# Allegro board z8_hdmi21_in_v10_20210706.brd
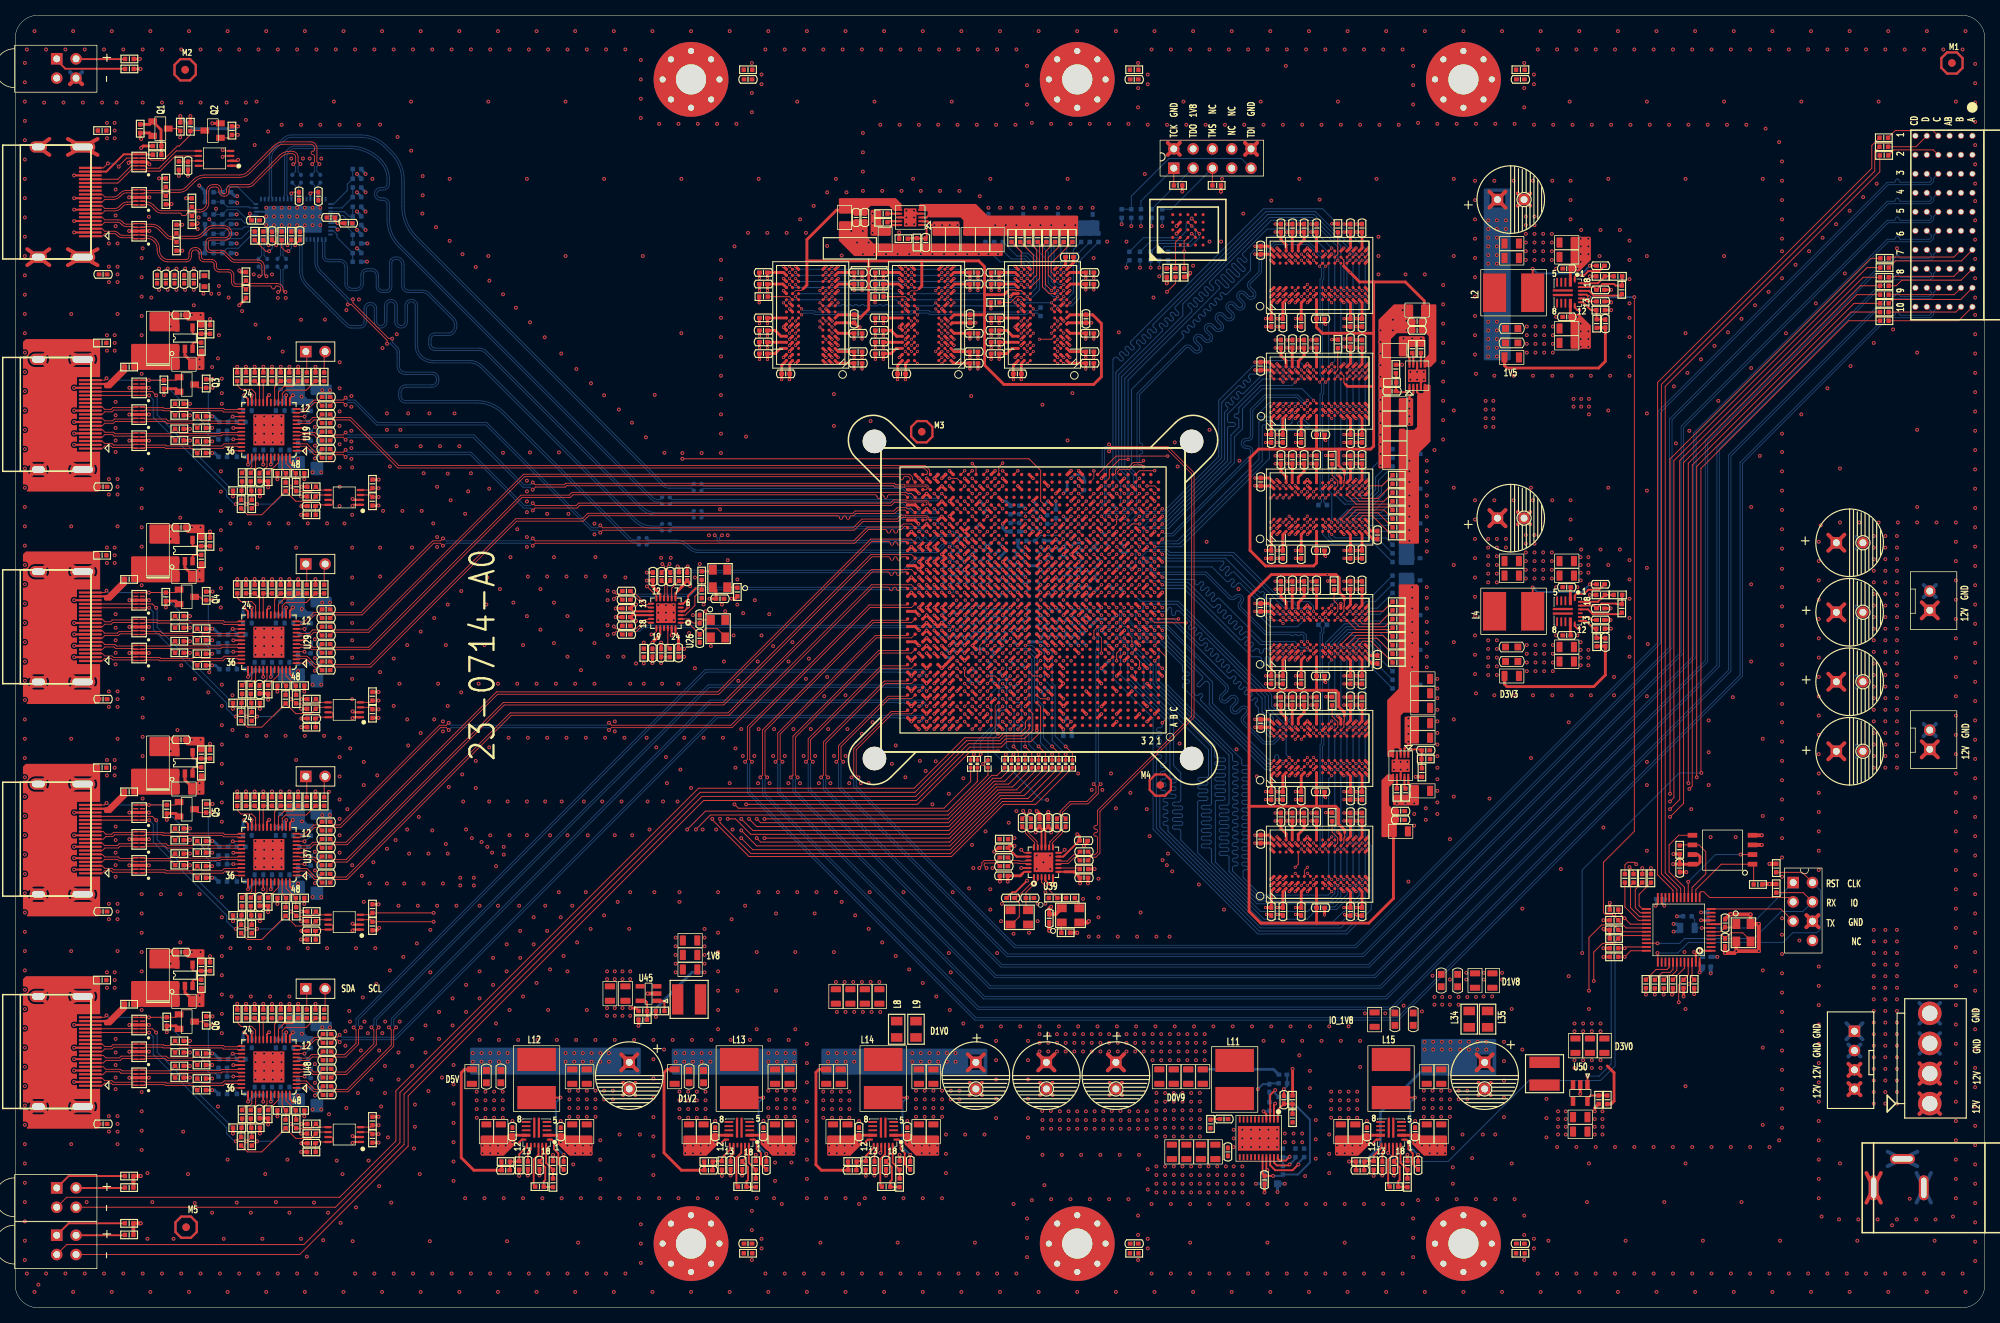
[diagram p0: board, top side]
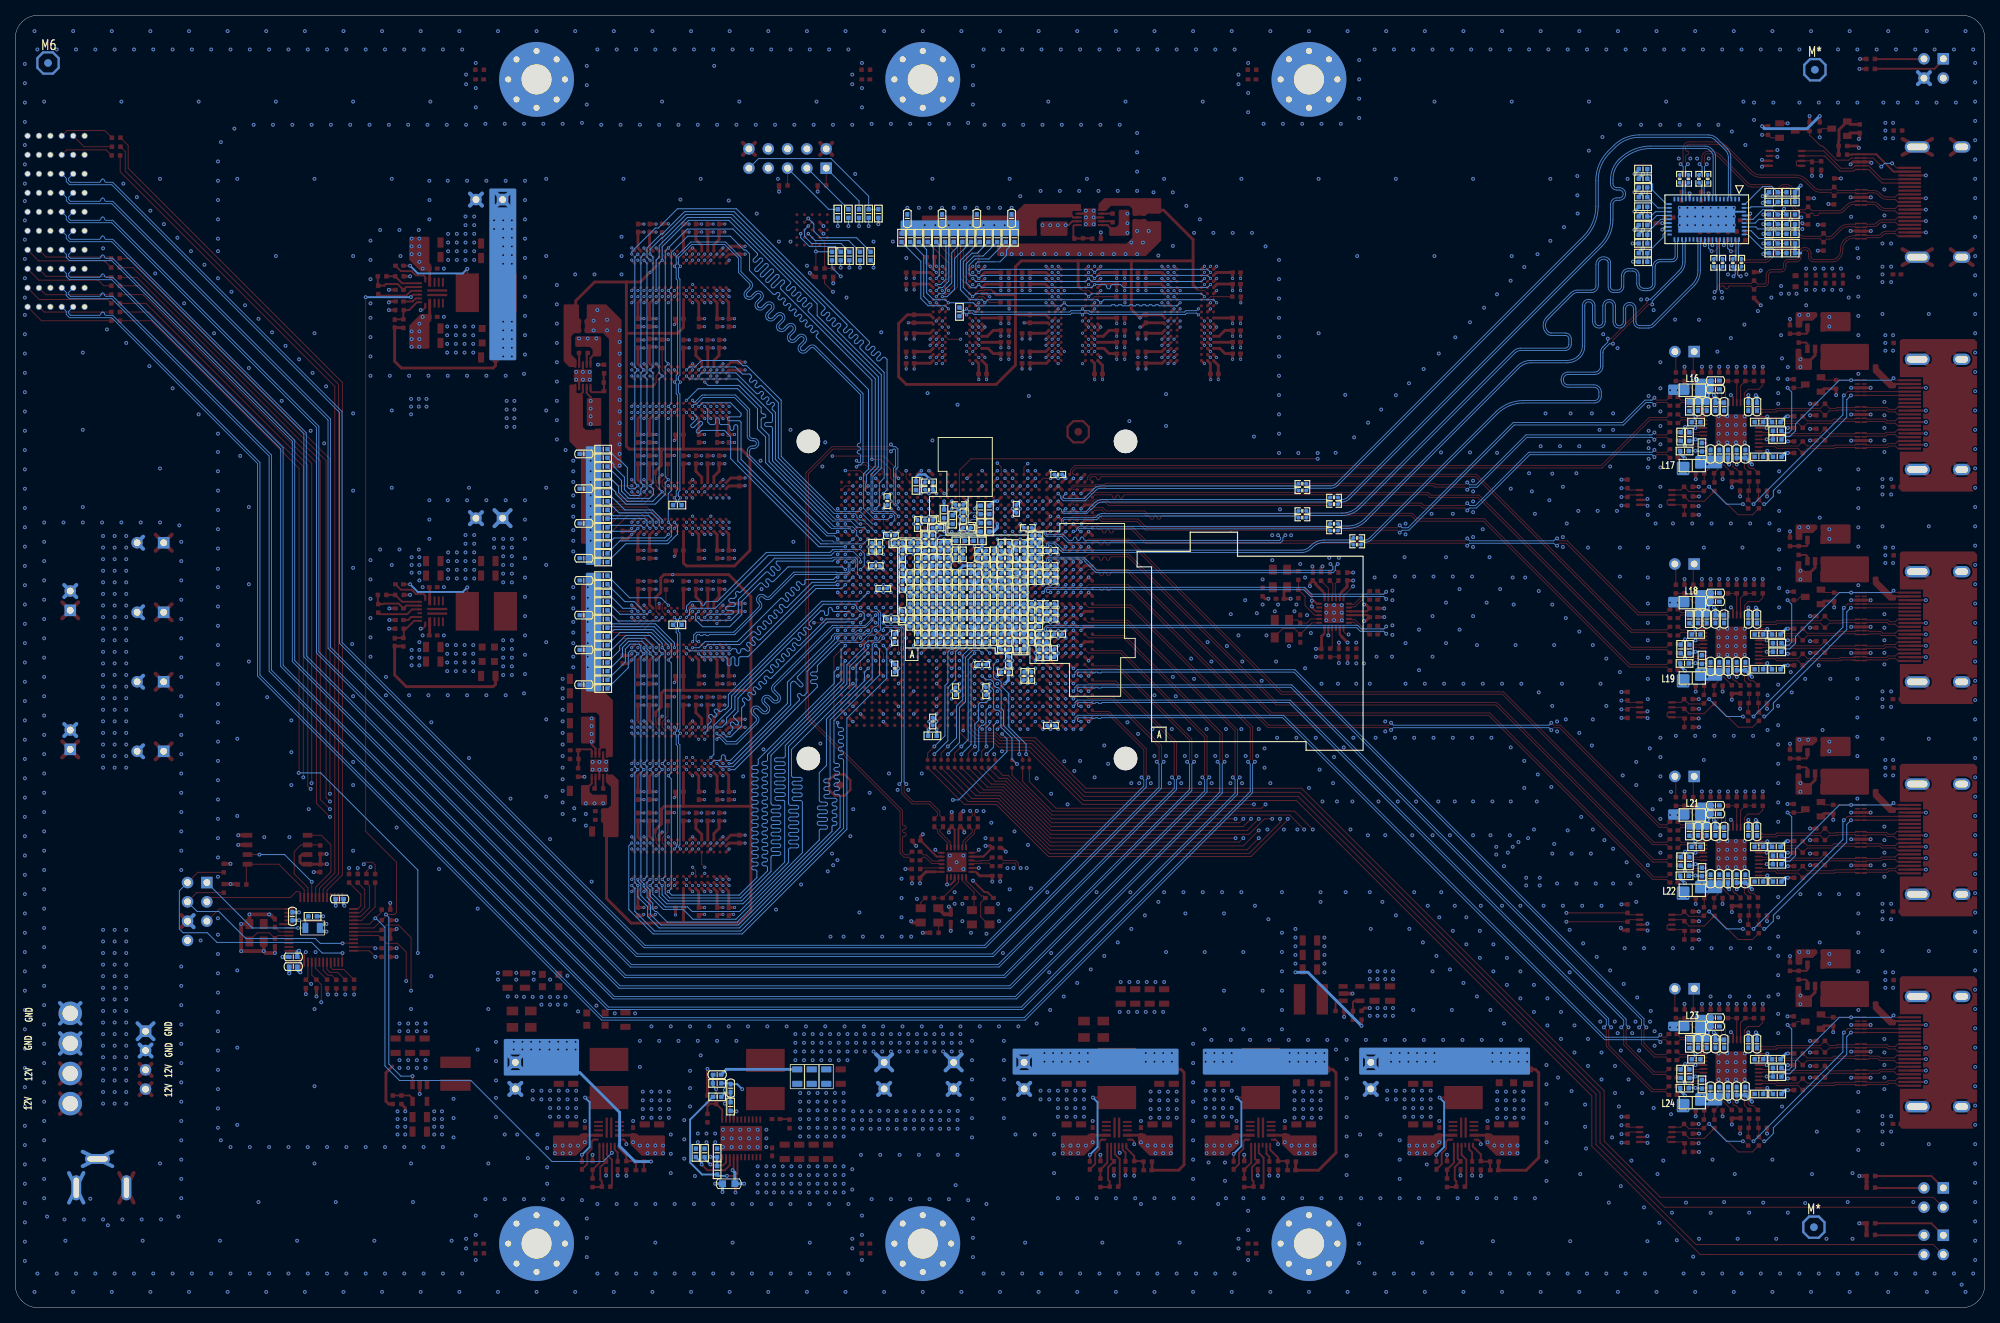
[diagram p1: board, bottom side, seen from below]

Outline 259.08 x 170.05 mm; copper layers: TOP, 02_GND1, 03_SIG1, 04_PWR1, 05_PWR2, 06_SIG2, 07_GND2, BOTTOM. Coordinates in mm from the lower left corner of the outline.
Outline path: 0,167 0,3.05 arc(0.89,0.89) 3.05,0 256.03,0 arc(258.19,0.89) 259.08,3.05 259.08,167 arc(258.19,169.16) 256.03,170.05 3.05,170.05 arc(0.89,169.16) 0,167

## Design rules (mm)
constraint set DEFAULT: min track width 0.127
net group CONN_RCK: nets CONN_RCK+ CONN_RCK-
net group CONN_TX0: nets CONN_TX+0 CONN_TX-0
net group CONN_TX1: nets CONN_TX+1 CONN_TX-1
net group CONN_TX2: nets CONN_TX+2 CONN_TX-2
net group CONN_TX3: nets CONN_TX+3 CONN_TX-3
net group CONN_TX4: nets CONN_TX+4 CONN_TX-4
net group CONN_TX5: nets CONN_TX+5 CONN_TX-5
net group CONN_TX6: nets CONN_TX+6 CONN_TX-6
net group CONN_TX7: nets CONN_TX+7 CONN_TX-7
net group CONN_TX_RCK: nets CONN_TX_RCK+ CONN_TX_RCK-
net group DDR3A: nets SI_DDR3A_N SI_DDR3A_P
net group DDR3A_133.33M: nets DDR3A_N DDR3A_P
net group DDR3B: nets SI_DDR3B_N SI_DDR3B_P
net group DDR3B_133.33M: nets DDR3B_N DDR3B_P
net group DDR3C: nets SI_DDR3C_N SI_DDR3C_P
net group DDR3C_133.33M: nets DDR3C_N DDR3C_P
net group HDMI20_RX_RCK+: nets HDMI20_RX_RCK+ HM20_RX_RCK+
net group HDMI20_RX_RCK-: nets HDMI20_RX_RCK- HM20_RX_RCK-
net group HDMI21_RX_RCK: nets HDMI21_RX_RCK+ HDMI21_RX_RCK-
net group HDMI_1_TCX: nets HDMI_1_TCX+ HDMI_1_TCX-
net group HDMI_1_TX0: nets HDMI_1_TX0+ HDMI_1_TX0-
net group HDMI_1_TX1: nets HDMI_1_TX1+ HDMI_1_TX1-
net group HDMI_1_TX2: nets HDMI_1_TX2+ HDMI_1_TX2-
net group HDMI_2_TCX: nets HDMI_2_TCX+ HDMI_2_TCX-
net group HDMI_2_TX0: nets HDMI_2_TX0+ HDMI_2_TX0-
net group HDMI_2_TX1: nets HDMI_2_TX1+ HDMI_2_TX1-
net group HDMI_2_TX2: nets HDMI_2_TX2+ HDMI_2_TX2-
net group HDMI_3_TCX: nets HDMI_3_TCX+ HDMI_3_TCX-
net group HDMI_3_TX0: nets HDMI_3_TX0+ HDMI_3_TX0-
net group HDMI_3_TX1: nets HDMI_3_TX1+ HDMI_3_TX1-
net group HDMI_3_TX2: nets HDMI_3_TX2+ HDMI_3_TX2-
net group HDMI_4_TCX: nets HDMI_4_TCX+ HDMI_4_TCX-
net group HDMI_4_TX0: nets HDMI_4_TX0+ HDMI_4_TX0-
net group HDMI_4_TX1: nets HDMI_4_TX1+ HDMI_4_TX1-
net group HDMI_4_TX2: nets HDMI_4_TX2+ HDMI_4_TX2-
net group HDMI_RX0N: nets HDMI_RX0N HDMI_RXC0N
net group HDMI_RX0P: nets HDMI_RX0P HDMI_RXC0P
net group HDMI_RX1N: nets HDMI_RX1N HDMI_RXC1N
net group HDMI_RX1P: nets HDMI_RX1P HDMI_RXC1P
net group HDMI_RX2N: nets HDMI_RX2N HDMI_RXC2N
net group HDMI_RX2P: nets HDMI_RX2P HDMI_RXC2P
net group HDMI_RX3N: nets HDMI_RX3N HDMI_RXC3N
net group HDMI_RX3P: nets HDMI_RX3P HDMI_RXC3P
net group HM20_TX: nets HM20_TX+ HM20_TX-
net group HM20_TX_RCX: nets HM20_TX_RCX+ HM20_TX_RCX-
net group HM21_RX0+: nets HM21_RX0+ HM21RX0+
net group HM21_RX0-: nets HM21_RX0- HM21RX0-
net group HM21_RX1+: nets HM21_RX1+ HM21RX1+
net group HM21_RX1-: nets HM21_RX1- HM21RX1-
net group HM21_RX2+: nets HM21_RX2+ HM21RX2+
net group HM21_RX2-: nets HM21_RX2- HM21RX2-
net group HM21_RX3+: nets HM21_RX3+ HM21RX3+
net group HM21_RX3-: nets HM21_RX3- HM21RX3-
net group HM_1_TCX+: nets HM_1_TCX+ N22318988
net group HM_1_TCX-: nets HM_1_TCX- N22318990
net group HM_1_TX0+: nets HM_1_TX0+ N22318294
net group HM_1_TX0-: nets HM_1_TX0- N22318980
net group HM_1_TX1+: nets HM_1_TX1+ N22318019
net group HM_1_TX1-: nets HM_1_TX1- N22318021
net group HM_1_TX2+: nets HM_1_TX2+ N22318023
net group HM_1_TX2-: nets HM_1_TX2- N22318025
net group HM_2_TCX+: nets HM_2_TCX+ N22337253
net group HM_2_TCX-: nets HM_2_TCX- N22337255
net group HM_2_TX0+: nets HM_2_TX0+ N22336562
net group HM_2_TX0-: nets HM_2_TX0- N22337251
net group HM_2_TX1+: nets HM_2_TX1+ N22336290
net group HM_2_TX1-: nets HM_2_TX1- N22336292
net group HM_2_TX2+: nets HM_2_TX2+ N22336294
net group HM_2_TX2-: nets HM_2_TX2- N22336296
net group HM_3_TCX+: nets HM_3_TCX+ N22342658
net group HM_3_TCX-: nets HM_3_TCX- N22342660
net group HM_3_TX0+: nets HM_3_TX0+ N22341967
net group HM_3_TX0-: nets HM_3_TX0- N22342656
net group HM_3_TX1+: nets HM_3_TX1+ N22341695
net group HM_3_TX1-: nets HM_3_TX1- N22341697
net group HM_3_TX2+: nets HM_3_TX2+ N22341699
net group HM_3_TX2-: nets HM_3_TX2- N22341701
net group HM_4_TCX+: nets HM_4_TCX+ N22347962
net group HM_4_TCX-: nets HM_4_TCX- N22347964
net group HM_4_TX0+: nets HM_4_TX0+ N22347259
net group HM_4_TX0-: nets HM_4_TX0- N22347960
net group HM_4_TX1+: nets HM_4_TX1+ N22346984
net group HM_4_TX1-: nets HM_4_TX1- N22347001
net group HM_4_TX2+: nets HM_4_TX2+ N22347003
net group HM_4_TX2-: nets HM_4_TX2- N22347005
net group RC_F: nets HDMI21_RX+ HDMI21_RX-
net group RC_F_: nets RC_F_N RC_F_P
net group REFCLK_F: nets REFCLK_F_N REFCLK_F_P
net group CLS_PWR_PH: nets D1V8 D3V3 D5V D12V VCC_D0V9 VCC_DDR3 VCCIO_D3V0 VCCR_D1V0 VDD_PLL1 VDD_PLL2 VREF_DDR3_A VREF_DDR3_B VREF_DDR3_C VTT_DDR3_A VTT_DDR3_B VTT_DDR3_C
net group DDR3_A: nets DDR3_A_A0 DDR3_A_A1 DDR3_A_A2 DDR3_A_A3 DDR3_A_A5 DDR3_A_A6 DDR3_A_A7 DDR3_A_A8 DDR3_A_A9 DDR3_A_A10 DDR3_A_A11 DDR3_A_A12 DDR3_A_BA0 DDR3_A_BA1 DDR3_A_BA2 DDR3_A_CAS_N_0 DDR3_A_CK_0 DDR3_A_CK_N_0 DDR3_A_CKE_0 DDR3_A_CS_N_0 DDR3_A_ODT_0 DDR3_A_RAS_N_0 DDR3_A_RST_N_0 DDR3_A_WE_N_0
net group DDR3_A_D0: nets DDR3_A_DM0 DDR3_A_DQ0 DDR3_A_DQ1 DDR3_A_DQ2 DDR3_A_DQ3 DDR3_A_DQ4 DDR3_A_DQ5 DDR3_A_DQ6 DDR3_A_DQ7 DDR3_A_DQS0N DDR3_A_DQS0P
net group DDR3_A_D1: nets DDR3_A_DM1 DDR3_A_DQ8 DDR3_A_DQ9 DDR3_A_DQ10 DDR3_A_DQ11 DDR3_A_DQ12 DDR3_A_DQ13 DDR3_A_DQ14 DDR3_A_DQ15 DDR3_A_DQS1N DDR3_A_DQS1P
net group DDR3_A_D2: nets DDR3_A_DM2 DDR3_A_DQ16 DDR3_A_DQ17 DDR3_A_DQ18 DDR3_A_DQ19 DDR3_A_DQ20 DDR3_A_DQ21 DDR3_A_DQ22 DDR3_A_DQ23 DDR3_A_DQS2N DDR3_A_DQS2P
net group DDR3_A_D3: nets DDR3_A_DM3 DDR3_A_DQ24 DDR3_A_DQ25 DDR3_A_DQ26 DDR3_A_DQ27 DDR3_A_DQ28 DDR3_A_DQ29 DDR3_A_DQ30 DDR3_A_DQ31 DDR3_A_DQS3N DDR3_A_DQS3P
net group DDR3_A_D4: nets DDR3_A_DM4 DDR3_A_DQ32 DDR3_A_DQ33 DDR3_A_DQ34 DDR3_A_DQ35 DDR3_A_DQ36 DDR3_A_DQ37 DDR3_A_DQ38 DDR3_A_DQ39 DDR3_A_DQS4N DDR3_A_DQS4P
net group DDR3_B_D0: nets DDR3_B_DM0 DDR3_B_DQ0 DDR3_B_DQ1 DDR3_B_DQ2 DDR3_B_DQ3 DDR3_B_DQ4 DDR3_B_DQ5 DDR3_B_DQ6 DDR3_B_DQ7 DDR3_B_DQS0N DDR3_B_DQS0P
net group DDR3_B_D1: nets DDR3_B_DM1 DDR3_B_DQ8 DDR3_B_DQ9 DDR3_B_DQ10 DDR3_B_DQ11 DDR3_B_DQ12 DDR3_B_DQ13 DDR3_B_DQ14 DDR3_B_DQ15 DDR3_B_DQS1N DDR3_B_DQS1P
net group DDR3_B_D2: nets DDR3_B_DM2 DDR3_B_DQ16 DDR3_B_DQ17 DDR3_B_DQ18 DDR3_B_DQ19 DDR3_B_DQ20 DDR3_B_DQ21 DDR3_B_DQ22 DDR3_B_DQ23 DDR3_B_DQS2N DDR3_B_DQS2P
net group DDR3_B_D3: nets DDR3_B_DM3 DDR3_B_DQ24 DDR3_B_DQ25 DDR3_B_DQ26 DDR3_B_DQ27 DDR3_B_DQ28 DDR3_B_DQ29 DDR3_B_DQ30 DDR3_B_DQ31 DDR3_B_DQS3N DDR3_B_DQS3P
net group DDR3_B_D4: nets DDR3_B_DM4 DDR3_B_DQ32 DDR3_B_DQ33 DDR3_B_DQ34 DDR3_B_DQ35 DDR3_B_DQ36 DDR3_B_DQ37 DDR3_B_DQ38 DDR3_B_DQ39 DDR3_B_DQS4N DDR3_B_DQS4P
net group DDR3_C_D0: nets DDR3_C_DM0 DDR3_C_DQ0 DDR3_C_DQ1 DDR3_C_DQ2 DDR3_C_DQ3 DDR3_C_DQ4 DDR3_C_DQ5 DDR3_C_DQ6 DDR3_C_DQ7 DDR3_C_DQS0N DDR3_C_DQS0P
net group DDR3_C_D1: nets DDR3_C_DM1 DDR3_C_DQ8 DDR3_C_DQ9 DDR3_C_DQ10 DDR3_C_DQ11 DDR3_C_DQ12 DDR3_C_DQ13 DDR3_C_DQ14 DDR3_C_DQ15 DDR3_C_DQS1N DDR3_C_DQS1P
net group DDR3_C_D2: nets DDR3_C_DM2 DDR3_C_DQ16 DDR3_C_DQ17 DDR3_C_DQ18 DDR3_C_DQ19 DDR3_C_DQ20 DDR3_C_DQ21 DDR3_C_DQ22 DDR3_C_DQ23 DDR3_C_DQS2N DDR3_C_DQS2P
net group DDR3_C_D3: nets DDR3_C_DM3 DDR3_C_DQ24 DDR3_C_DQ25 DDR3_C_DQ26 DDR3_C_DQ27 DDR3_C_DQ28 DDR3_C_DQ29 DDR3_C_DQ30 DDR3_C_DQ31 DDR3_C_DQS3N DDR3_C_DQS3P
net group DDR3_C_D4: nets DDR3_C_DM4 DDR3_C_DQ32 DDR3_C_DQ33 DDR3_C_DQ34 DDR3_C_DQ35 DDR3_C_DQ36 DDR3_C_DQ37 DDR3_C_DQ38 DDR3_C_DQ39 DDR3_C_DQS4N DDR3_C_DQS4P
net group N22030720: nets N22030720
net group N22031163: nets N22031488
net group N22449835: nets N22449835
net group N22451844: nets N22451844
net group N22647875: nets N22647875
net group N22766094: nets N22766094
net group N22768239: nets N22768239

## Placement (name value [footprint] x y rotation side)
C1  0.1uF  [C0402]  96.39 161.61 0 top
C2  0.1uF  [C0402]  147.19 161.61 0 top
C3  0.1uF  [C0402]  197.99 161.61 0 top
C4  0.1uF  [C0402]  22.73 150.24 90 top
C5  0.1uF  [C0402]  37.34 146.24 270 top
C6  0.1uF  [C0402]  39.88 146.24 270 top
C7  270uF-NCC  [CAP196_POL_3_5MM]  196.72 145.8 0 top
C8  0.1uF  [C0402]  41.53 143.45 0 top
C9  10uF-08  [C0805]  109.09 143.45 270 top
C10  0.1uF  [C0402]  110.62 143.45 270 top
C11  0.1uF  [C0402]  111.76 143.45 270 top
C12  0.1uF  [C0402]  31.62 143.07 0 top
C13  1uF  [C0402]  43.82 142.68 180 top
C14  0.1uF  [C0402]  166.5 142.05 90 top
C15  0.1uF  [C0402]  168.02 142.05 90 top
C16  0.1uF  [C0402]  169.55 142.05 90 top
C17  0.1uF  [C0402]  171.2 142.05 90 top
C18  0.1uF  [C0402]  175.64 142.05 90 top
C19  0.1uF  [C0402]  177.16 142.05 90 top
C20  0.1uF  [C0402]  33.78 141.03 90 top
C21  0.1uF  [C0402]  37.47 141.03 90 top
C22  10uF-08  [C0805]  114.43 140.53 270 top
C23  10uF-08  [C0805]  121.41 140.53 270 top
C24  10uF-08  [C0805]  123.32 140.53 270 top
C25  10uF-08  [C0805]  125.35 140.53 270 top
C26  10uF-08  [C0805]  127.25 140.53 270 top
C27  10uF-08  [C0805]  129.16 140.53 270 top
C28  1nF  [C0402]  119.76 140.14 90 top
C29  22uF-08  [C0805]  204.09 140.14 180 top
C30  47uF-08  [C0805]  196.85 140.02 0 top
C31  0.1uF  [C0402]  163.83 139.13 90 top
C32  5pF-NC  [C0402]  138.68 138.24 0 top
C33  22uF-08  [C0805]  204.09 138.24 180 top
C34  47uF-08  [C0805]  196.85 138.11 0 top
C35  0.1uF  [C0402]  208.53 137.1 180 top
C36  0.1uF  [C0402]  204.09 136.72 180 top
C37  0.1uF  [C0402]  98.42 136.21 180 top
C38  0.1uF  [C0402]  110.87 136.21 0 top
C39  0.1uF  [C0402]  113.67 136.21 180 top
C40  0.1uF  [C0402]  126.11 136.21 0 top
C41  0.1uF  [C0402]  128.91 136.21 180 top
C42  0.1uF  [C0402]  141.35 136.21 0 top
C43  0.1uF_06  [C0402]  11.56 135.95 0 top
C44  0.1uF  [C0402]  18.67 135.32 90 top
C45  0.1uF  [C0402]  19.81 135.32 90 top
C46  0.1uF  [C0402]  20.95 135.32 90 top
C49  10uF  [C0402]  23.49 135.32 90 top
C50  0.1uF  [C0402]  98.42 134.68 180 top
C51  0.1uF  [C0402]  110.87 134.68 0 top
C52  0.1uF  [C0402]  113.67 134.68 180 top
C53  0.1uF  [C0402]  126.11 134.68 0 top
C54  0.1uF  [C0402]  128.91 134.68 180 top
C55  0.1uF  [C0402]  141.35 134.68 0 top
C56  4.7uF  [C0402]  208.53 133.92 0 top
C57  47nF  [C0402]  208.53 132.4 0 top
C58  10uF-08  [C0805]  184.4 131.25 180 top
C59  0.1uF  [C0402]  21.82 130.61 180 top
C60  0.1uF  [C0402]  204.09 130.37 180 top
C61  0.1uF  [C0402]  98.42 130.24 180 top
C62  0.1uF  [C0402]  113.67 130.24 180 top
C63  0.1uF  [C0402]  128.91 130.24 180 top
C64  0.1uF  [C0402]  110.36 130.11 270 top
C65  0.1uF  [C0402]  125.6 130.11 270 top
C66  0.1uF  [C0402]  140.84 130.11 270 top
C67  0.1uF  [C0402]  171.7 130.11 0 top
C68  0.1uF  [C0402]  184.4 129.73 180 top
C69  0.1uF  [C0402]  165.23 129.6 270 top
C70  0.1uF  [C0402]  166.75 129.6 270 top
C71  0.1uF  [C0402]  169.16 129.6 270 top
C72  0.1uF  [C0402]  175.64 129.6 270 top
C73  0.1uF  [C0402]  177.16 129.6 270 top
C74  56pF  [C0402]  209.17 129.48 90 top
C75  4.7uF-08  [C0603]  196.85 128.84 0 top
C76  22uF-08  [C0805]  204.09 128.84 180 top
C77  0.1uF  [C0402]  98.42 128.59 180 top
C78  0.1uF  [C0402]  113.67 128.59 180 top
C79  0.1uF  [C0402]  128.91 128.59 180 top
C80  0.1uF  [C0402]  184.4 128.59 180 top
C81  0.1uF  [C0402]  110.87 128.21 0 top
C82  0.1uF  [C0402]  126.11 128.21 0 top
C83  0.1uF  [C0402]  141.35 128.21 0 top
C84  0.1uF  [C0402]  98.42 127.06 180 top
C85  0.1uF  [C0402]  113.67 127.06 180 top
C86  0.1uF  [C0402]  128.91 127.06 180 top
C87  0.1uF  [C0402]  175.64 126.94 90 top
C88  4.7uF-08  [C0603]  196.85 126.94 0 top
C89  22uF-08  [C0805]  204.09 126.94 180 top
C90  0.1uF  [C0402]  166.5 126.81 90 top
C91  0.1uF  [C0402]  168.02 126.81 90 top
C92  0.1uF  [C0402]  169.55 126.81 90 top
C93  0.1uF  [C0402]  171.2 126.81 90 top
C94  0.1uF  [C0402]  177.16 126.81 90 top
C95  10uF-08  [C0805]  181.48 125.92 180 top
C96  0.1uF  [C0402]  110.87 125.79 0 top
C97  0.1uF  [C0402]  126.11 125.79 0 top
C98  0.1uF  [C0402]  141.35 125.79 0 top
C99  0.1uF  [C0402]  98.42 125.54 180 top
C100  0.1uF  [C0402]  113.67 125.54 180 top
C101  0.1uF  [C0402]  128.91 125.54 180 top
C102  47uF-08  [C0805]  196.85 125.03 0 top
C103  0.1uF  [C0402]  110.87 124.27 0 top
C104  0.1uF  [C0402]  126.11 124.27 0 top
C105  0.1uF  [C0402]  141.35 124.27 0 top
C106  10uF-08  [C0805]  22.2 124.14 0 top
C107  0.1uF  [C0402]  163.83 123.89 90 top
C108  0.1uF  [C0402]  101.35 122.87 180 top
C109  0.1uF  [C0402]  116.59 122.87 180 top
C110  0.1uF  [C0402]  131.83 122.87 180 top
C111  1nF  [C0402]  181.1 120.59 0 top
C113  0.1uF  [C0402]  40.89 119.82 180 top
C114  10uF-08  [C0805]  181.48 118.94 180 top
C115  0.1uF  [C0402]  40.89 118.68 180 top
C117  0.1uF  [C0402]  40.89 117.54 180 top
C118  10uF-08  [C0805]  181.48 117.03 180 top
C120  0.1uF  [C0402]  40.89 116.4 180 top
C122  0.1uF  [C0402]  40.89 115.25 180 top
C123  10uF-08  [C0805]  181.48 115 180 top
C124  0.1uF  [C0402]  171.7 114.87 0 top
C125  0.1uF  [C0402]  165.23 114.36 270 top
C126  0.1uF  [C0402]  166.75 114.36 270 top
C127  0.1uF  [C0402]  169.16 114.36 270 top
C128  0.1uF  [C0402]  175.64 114.36 270 top
C129  0.1uF  [C0402]  177.16 114.36 270 top
C130  0.1uF  [C0402]  40.89 114.11 180 top
C131  10uF-08  [C0805]  181.48 113.09 180 top
C132  0.1uF  [C0402]  40.89 112.97 180 top
C133  0.1uF  [C0402]  40.89 111.82 180 top
C134  0.1uF  [C0402]  166.5 111.57 90 top
C135  0.1uF  [C0402]  168.02 111.57 90 top
C136  0.1uF  [C0402]  169.55 111.57 90 top
C137  0.1uF  [C0402]  171.2 111.57 90 top
C138  0.1uF  [C0402]  175.64 111.57 90 top
C139  0.1uF  [C0402]  177.16 111.57 90 top
C140  10uF-08  [C0805]  181.48 111.19 180 top
C141  0.1uF  [C0402]  32.13 109.28 270 top
C142  0.1uF  [C0402]  163.83 108.65 90 top
C143  0.1uF_06  [C0402]  11.56 108.01 0 top
C144  0.1uF  [C0402]  38.96 105.47 0 top
C145  270uF-NCC  [CAP196_POL_3_5MM]  196.72 103.89 0 top
C146  0.1uF  [C0402]  21.82 102.67 180 top
C147  5pF-NC  [C0402]  179.2 101.66 270 top
C148  270uF-NCC  [CAP196_POL_3_5MM]  241.3 100.65 0 top
C149  0.1uF  [C0402]  171.7 99.63 0 top
C150  0.1uF  [C0402]  165.23 99.12 270 top
C151  0.1uF  [C0402]  166.75 99.12 270 top
C152  0.1uF  [C0402]  169.16 99.12 270 top
C153  0.1uF  [C0402]  175.64 99.12 270 top
C154  0.1uF  [C0402]  177.16 99.12 270 top
C155  47uF-08  [C0805]  196.85 98.23 0 top
C156  22uF-08  [C0805]  204.09 98.23 180 top
C157  47uF-08  [C0805]  196.85 96.33 0 top
C158  22uF-08  [C0805]  204.09 96.33 180 top
C159  0.1uF  [C0402]  83.88 96.2 90 top
C160  0.1uF  [C0402]  85.03 96.2 90 top
C161  0.1uF  [C0402]  86.17 96.2 90 top
C162  0.1uF  [C0402]  88.39 96.2 90 top
C163  10uF-08  [C0805]  22.2 96.2 0 top
C164  0.1uF  [C0402]  208.53 95.19 180 top
C165  0.1uF  [C0402]  166.5 95.06 90 top
C166  0.1uF  [C0402]  168.02 95.06 90 top
C167  0.1uF  [C0402]  169.55 95.06 90 top
C168  0.1uF  [C0402]  171.2 95.06 90 top
C169  0.1uF  [C0402]  175.64 95.06 90 top
C170  0.1uF  [C0402]  177.16 95.06 90 top
C171  0.1uF  [C0402]  204.09 94.81 180 top
C172  0.1uF  [C0402]  80.39 94.3 180 top
C173  0.1uF  [C0402]  92.71 93.28 0 top
C174  0.1uF  [C0402]  80.39 93.15 180 top
C175  0.1uF  [C0402]  163.83 92.14 90 top
C176  0.1uF  [C0402]  80.39 92.01 180 top
C177  4.7uF  [C0402]  208.53 92.01 0 top
C178  0.1uF  [C0402]  40.89 91.88 180 top
C179  270uF-NCC  [CAP196_POL_3_5MM]  241.3 91.5 0 top
C180  0.1uF  [C0402]  80.39 90.87 180 top
C181  0.1uF  [C0402]  40.89 90.74 180 top
C182  20pF  [C0402]  90.04 90.61 270 top
C183  47nF  [C0402]  208.53 90.49 0 top
C184  0.1uF  [C0402]  80.39 89.73 180 top
C185  0.1uF  [C0402]  40.89 89.6 180 top
C186  0.1uF  [C0402]  80.39 88.58 180 top
C187  0.1uF  [C0402]  40.89 88.46 180 top
C188  0.1uF  [C0402]  204.09 88.46 180 top
C189  20pF  [C0402]  90.04 88.07 90 top
C190  56pF  [C0402]  209.17 87.57 90 top
C191  0.1uF  [C0402]  40.89 87.31 180 top
C192  4.7uF-08  [C0603]  196.85 86.93 0 top
C193  22uF-08  [C0805]  204.09 86.93 180 top
C194  0.1uF  [C0402]  40.89 86.17 180 top
C195  0.1uF  [C0402]  83.82 86.17 270 top
C196  3.3pF  [C0402]  84.96 86.17 270 top
C197  0.1uF  [C0402]  87.25 86.17 270 top
C198  5pF-NC  [C0402]  179.2 85.28 270 top
C199  0.1uF  [C0402]  40.89 85.03 180 top
C200  4.7uF-08  [C0603]  196.85 85.03 0 top
C201  22uF-08  [C0805]  204.09 85.03 180 top
C202  0.1uF  [C0402]  40.89 83.88 180 top
C203  0.1uF  [C0402]  171.7 83.12 0 top
C204  47uF-08  [C0805]  196.85 83.12 0 top
C205  10uF-08  [C0805]  185.17 82.74 0 top
C206  0.1uF  [C0402]  165.23 82.61 270 top
C207  0.1uF  [C0402]  166.75 82.61 270 top
C208  0.1uF  [C0402]  169.16 82.61 270 top
C209  0.1uF  [C0402]  175.64 82.61 270 top
C210  0.1uF  [C0402]  177.16 82.61 270 top
C211  270uF-NCC  [CAP196_POL_3_5MM]  241.3 82.36 0 top
C212  0.1uF  [C0402]  32.13 81.34 270 top
C213  10uF-08  [C0805]  185.17 80.84 0 top
C214  0.1uF_06  [C0402]  11.56 80.07 0 top
C215  0.1uF  [C0402]  166.5 79.82 90 top
C216  0.1uF  [C0402]  168.02 79.82 90 top
C217  0.1uF  [C0402]  169.55 79.82 90 top
C218  0.1uF  [C0402]  171.2 79.82 90 top
C219  0.1uF  [C0402]  175.64 79.82 90 top
C220  0.1uF  [C0402]  177.16 79.82 90 top
C221  10uF-08  [C0805]  185.17 78.93 0 top
C222  0.1uF  [C0402]  38.96 77.53 0 top
C223  0.1uF  [C0402]  163.83 76.9 90 top
C224  10uF-08  [C0805]  185.17 76.9 0 top
C225  10uF-08  [C0805]  185.17 74.99 0 top
C226  0.1uF  [C0402]  21.82 74.73 180 top
C227  270uF-NCC  [CAP196_POL_3_5MM]  241.3 73.22 0 top
C228  0.1uF  [C0402]  185.55 73.34 180 top
C229  10uF-08  [C0805]  22.2 68.26 0 top
C230  10uF-08  [C0805]  185.17 68.01 0 top
C231  0.1uF  [C0402]  171.7 67.88 0 top
C232  0.1uF  [C0402]  165.23 67.37 270 top
C233  0.1uF  [C0402]  166.75 67.37 270 top
C234  0.1uF  [C0402]  169.16 67.37 270 top
C235  0.1uF  [C0402]  175.64 67.37 270 top
C236  0.1uF  [C0402]  177.16 67.37 270 top
C237  0.1uF  [C0402]  182.25 65.34 0 top
C238  0.1uF  [C0402]  166.5 64.58 90 top
C239  0.1uF  [C0402]  168.02 64.58 90 top
C240  0.1uF  [C0402]  169.55 64.58 90 top
C241  0.1uF  [C0402]  171.2 64.58 90 top
C242  0.1uF  [C0402]  175.64 64.58 90 top
C243  0.1uF  [C0402]  177.16 64.58 90 top
C244  0.1uF  [C0402]  182.25 64.2 0 top
C245  0.1uF  [C0402]  40.89 63.94 180 top
C246  0.1uF  [C0402]  132.46 63.82 90 top
C247  0.1uF  [C0402]  133.6 63.82 90 top
C248  0.1uF  [C0402]  134.75 63.82 90 top
C249  0.1uF  [C0402]  135.89 63.82 90 top
C250  0.1uF  [C0402]  137.03 63.82 90 top
C251  0.1uF  [C0402]  138.18 63.82 90 top
C252  0.1uF  [C0402]  40.89 62.8 180 top
C253  10uF-08  [C0805]  182.25 62.67 0 top
C254  0.1uF  [C0402]  40.89 61.66 180 top
C255  0.1uF  [C0402]  163.83 61.66 90 top
C256  0.1uF  [C0402]  140.54 61.46 0 top
C257  0.1uF  [C0402]  40.89 60.52 180 top
C258  0.1uF  [C0402]  130.05 60.52 180 top
C259  0.1uF  [C0402]  140.59 60.01 0 top
C260  0.1uF  [C0402]  40.89 59.37 180 top
C261  0.1uF  [C0402]  130.05 59.25 180 top
C262  0.1uF  [C0402]  140.59 58.86 0 top
C263  0.1uF  [C0402]  40.89 58.23 180 top
C264  0.1uF  [C0402]  130.05 58.1 180 top
C265  0.1uF  [C0402]  218.95 57.85 270 top
C266  0.1uF  [C0402]  40.89 57.09 180 top
C267  0.1uF  [C0402]  130.05 56.83 180 top
C268  0.1uF  [C0402]  140.59 56.58 0 top
C269  0.1uF  [C0402]  40.89 55.94 180 top
C270  20pF  [C0402]  130.94 53.91 0 top
C271  20pF  [C0402]  133.48 53.91 180 top
C272  0.1uF  [C0402]  32.13 53.4 270 top
C273  0.1uF  [C0402]  171.7 52.64 0 top
C274  0.1uF_06  [C0402]  11.56 52.13 0 top
C275  0.1uF  [C0402]  165.23 52.13 270 top
C276  0.1uF  [C0402]  166.75 52.13 270 top
C277  0.1uF  [C0402]  169.16 52.13 270 top
C278  0.1uF  [C0402]  175.64 52.13 270 top
C279  0.1uF  [C0402]  177.16 52.13 270 top
C280  0.1uF  [C0402]  136.02 51.24 270 top
C281  20pF  [C0402]  224.92 50.61 270 top
C282  0.1uF  [C0402]  38.96 49.59 0 top
C283  10uF-08  [C0805]  88.77 48.32 180 top
C284  20pF  [C0402]  224.92 48.07 90 top
C285  0.1uF  [C0402]  21.82 46.79 180 top
C286  10uF-08  [C0805]  88.77 46.42 180 top
C287  10uF-08  [C0805]  88.77 44.51 180 top
C288  10uF-08  [C0805]  78.23 41.34 270 top
C289  10uF-08/NC  [C0805]  80.26 41.34 270 top
C290  47uF-08  [C0805]  107.95 40.96 90 top
C291  47uF-08  [C0805]  109.86 40.96 90 top
C292  47uF-08  [C0805]  111.76 40.96 90 top
C293  47uF-08  [C0805]  113.67 40.96 90 top
C294  10uF-08  [C0805]  22.2 40.32 0 top
C295  0.1uF  [C0402]  41.02 36 180 top
C296  0.1uF  [C0402]  41.02 34.86 180 top
C297  10uF-08  [C0805]  205.23 34.48 90 top
C298  10uF-08  [C0805]  207.14 34.48 90 top
C299  10uF-08  [C0805]  209.04 34.48 90 top
C300  0.1uF  [C0402]  41.02 33.72 180 top
C301  0.1uF  [C0402]  41.02 32.58 180 top
C302  0.1uF  [C0402]  41.02 31.43 180 top
C303  270uF-NCC  [CAP196_POL_3_5MM]  80.77 30.54 270 top
C304  270uF-NCC  [CAP196_POL_3_5MM]  126.36 30.54 270 top
C305  270uF-NCC  [CAP196_POL_3_5MM]  135.64 30.54 270 top
C306  270uF-NCC  [CAP196_POL_3_5MM]  144.78 30.54 270 top
C307  270uF-NCC  [CAP196_POL_3_5MM]  193.29 30.54 270 top
C308  47uF-08  [C0805]  150.5 30.42 270 top
C309  47uF-08  [C0805]  152.4 30.42 270 top
C310  47uF-08  [C0805]  154.31 30.42 270 top
C311  47uF-08  [C0805]  156.21 30.42 270 top
C312  47uF-08  [C0805]  60.07 30.42 270 top
C313  4.7uF-08  [C0603]  61.98 30.42 270 top
C314  4.7uF-08  [C0603]  63.88 30.42 270 top
C315  47uF-08  [C0805]  73.28 30.42 270 top
C316  47uF-08  [C0805]  75.18 30.42 270 top
C317  47uF-08  [C0805]  86.74 30.42 270 top
C318  4.7uF-08  [C0603]  88.65 30.42 270 top
C319  4.7uF-08  [C0603]  90.55 30.42 270 top
C320  47uF-08  [C0805]  99.95 30.42 270 top
C321  47uF-08  [C0805]  101.85 30.42 270 top
C322  47uF-08  [C0805]  106.68 30.42 270 top
C323  47uF-08  [C0805]  108.59 30.42 270 top
C324  47uF-08  [C0805]  118.87 30.42 270 top
C325  47uF-08  [C0805]  120.78 30.42 270 top
C326  47uF-08  [C0805]  178.82 37.91 90 top
C327  4.7uF-08  [C0603]  181.48 37.97 90 top
C328  4.7uF-08  [C0603]  183.9 37.97 90 top
C329  47uF-08  [C0805]  185.67 30.42 270 top
C330  47uF-08  [C0805]  187.58 30.42 270 top
C331  0.1uF  [C0402]  41.02 30.29 180 top
C332  0.1uF  [C0402]  41.02 29.15 180 top
C333  0.1uF  [C0402]  41.02 28 180 top
C334  1nF  [C0402]  166.88 27.37 90 top
C335  0.1uF  [C0402]  32.13 25.46 270 top
C336  2.2nF  [C0402]  159 24.83 0 top
C337  10uF-08  [C0805]  205.87 25.08 0 top
C338  0.1uF_06  [C0402]  11.56 24.19 0 top
C339  22uF-08  [C0805]  61.98 23.18 90 top
C340  22uF-08  [C0805]  63.88 23.18 90 top
C341  0.1uF  [C0402]  65.41 23.18 90 top
C342  0.1uF  [C0402]  71.75 23.18 90 top
C343  22uF-08  [C0805]  73.28 23.18 90 top
C344  22uF-08  [C0805]  75.18 23.18 90 top
C345  22uF-08  [C0805]  88.65 23.18 90 top
C346  22uF-08  [C0805]  90.55 23.18 90 top
C347  0.1uF  [C0402]  92.08 23.18 90 top
C348  0.1uF  [C0402]  98.42 23.18 90 top
C349  22uF-08  [C0805]  99.95 23.18 90 top
C350  22uF-08  [C0805]  101.85 23.18 90 top
C351  22uF-08  [C0805]  107.57 23.18 90 top
C352  22uF-08  [C0805]  109.47 23.18 90 top
C353  0.1uF  [C0402]  111 23.18 90 top
C354  0.1uF  [C0402]  117.35 23.18 90 top
C355  22uF-08  [C0805]  118.87 23.18 90 top
C356  22uF-08  [C0805]  120.78 23.18 90 top
C357  22uF-08  [C0805]  174.37 23.18 90 top
C358  22uF-08  [C0805]  176.28 23.18 90 top
C359  0.1uF  [C0402]  177.8 23.18 90 top
C360  0.1uF  [C0402]  184.15 23.18 90 top
C361  22uF-08  [C0805]  185.67 23.18 90 top
C362  22uF-08  [C0805]  187.58 23.18 90 top
C363  10uF-08  [C0805]  205.87 23.18 0 top
C364  0.1uF  [C0402]  38.96 21.65 0 top
C365  22uF-08  [C0805]  152.15 20.51 90 top
C366  22uF-08  [C0805]  154.05 20.51 90 top
C367  22uF-08  [C0805]  155.96 20.51 90 top
C368  22uF-08  [C0805]  157.86 20.51 90 top
C369  0.1uF  [C0402]  159.51 20.51 90 top
C370  47nF  [C0402]  67.44 18.73 270 top
C371  4.7uF  [C0402]  68.96 18.73 270 top
C372  0.1uF  [C0402]  72.14 18.73 90 top
C373  47nF  [C0402]  94.11 18.73 270 top
C374  4.7uF  [C0402]  95.63 18.73 270 top
C375  0.1uF  [C0402]  98.81 18.73 90 top
C376  47nF  [C0402]  113.03 18.73 270 top
C377  4.7uF  [C0402]  114.55 18.73 270 top
C378  0.1uF  [C0402]  117.73 18.73 90 top
C379  47nF  [C0402]  179.83 18.73 270 top
C380  4.7uF  [C0402]  181.36 18.73 270 top
C381  0.1uF  [C0402]  184.53 18.73 90 top
C382  56pF  [C0402]  64.52 18.1 0 top
C383  56pF  [C0402]  91.19 18.1 0 top
C384  56pF  [C0402]  110.11 18.1 0 top
C385  56pF  [C0402]  176.91 18.1 0 top
C386  1uF  [C0402]  164.34 16.83 270 top
C387  0.1uF  [C0402]  96.39 8.45 0 top
C388  0.1uF  [C0402]  147.19 8.45 0 top
C389  0.1uF  [C0402]  197.99 8.45 0 top
C390  0.1uF  [C0402-8]  40.13 148.53 270 bottom
C391  0.1uF  [C0402-8]  38.99 148.53 270 bottom
C392  0.1uF  [C0402-8]  37.59 148.53 270 bottom
C393  0.1uF  [C0402-8]  36.45 148.53 270 bottom
C394  0.1uF  [C0402]  141.73 143.32 90 bottom
C395  0.1uF  [C0402]  137.16 143.32 90 bottom
C396  0.1uF  [C0402]  132.59 143.32 90 bottom
C397  0.1uF  [C0402]  128.02 143.32 90 bottom
C398  0.1uF  [C0402-8]  35.64 137.49 90 bottom
C399  0.1uF  [C0402-8]  34.49 137.49 90 bottom
C400  0.1uF  [C0402-8]  33.15 137.49 90 bottom
C401  0.1uF  [C0402-8]  32 137.49 90 bottom
C402  0.1uF  [C0402]  35.43 121.98 0 bottom
C403  0.1uF  [C0402]  35.43 120.84 0 bottom
C404  10uF  [C0402]  37.72 118.55 90 bottom
C405  0.1uF  [C0402]  36.58 118.55 90 bottom
C406  0.01uF  [C0402]  35.43 118.55 90 bottom
C407  0.1uF  [C0402]  34.29 118.55 90 bottom
C408  10uF  [C0402]  31.12 118.55 90 bottom
C409  0.1uF  [C0402]  29.97 118.55 90 bottom
C410  0.1uF  [C0402]  184.28 112.33 0 bottom
C411  0.01uF  [C0402]  36.07 112.33 270 bottom
C412  0.1uF  [C0402]  34.92 112.33 270 bottom
C413  0.01uF  [C0402]  33.78 112.33 270 bottom
C414  0.1uF  [C0402]  32.64 112.33 270 bottom
C415  0.1uF  [C0402]  31.5 112.33 270 bottom
C417  0.1uF  [C0402]  184.28 107.76 0 bottom
C421  4.7uF  [C0402-8]  134.88 105.62 180 bottom
C423  0.1uF  [C0402-8]  127.39 105.12 90 bottom
C425  0.1uF  [C0402-8]  134.39 104.12 90 bottom
C426  0.1uF  [C0402-8]  82.55 101.28 0 bottom
C427  0.1uF  [C0402]  184.28 103.19 0 bottom
C428  0.1uF  [C0402-8]  82.55 100.39 0 bottom
C429  0.1uF  [C0402-8]  133.88 102.62 180 bottom
C430  4.7uF  [C0402-8]  125.89 102.62 180 bottom
C432  0.1uF  [C0402-8]  124.89 101.62 0 bottom
C433  0.1uF  [C0402-8]  143.89 101.62 0 bottom
C434  0.1uF  [C0402-8]  124.89 100.62 0 bottom
C436  0.1uF  [C0402-8]  139.39 101.12 270 bottom
C437  0.1uF  [C0402-8]  142.89 100.62 180 bottom
C438  4.7uF  [C0402-8]  140.89 100.62 180 bottom
C439  0.1uF  [C0402-8]  126.89 100.62 0 bottom
C440  0.1uF  [C0402-8]  137.39 100.13 90 bottom
C441  4.7uF  [C0402-8]  146.39 100.12 90 bottom
C442  0.1uF  [C0402-8]  145.39 100.12 90 bottom
C443  0.1uF  [C0402-8]  136.39 100.12 90 bottom
C444  0.1uF  [C0402-8]  129.39 100.12 90 bottom
C445  0.1uF  [C0402-8]  128.39 100.12 90 bottom
C446  0.1uF  [C0402-8]  131.89 99.62 180 bottom
C447  0.1uF  [C0402-8]  122.89 99.62 180 bottom
C448  0.1uF  [C0402-8]  140.89 99.62 0 bottom
C449  0.1uF  [C0402-8]  124.89 99.62 0 bottom
C450  0.1uF  [C0402-8]  138.89 99.62 0 bottom
C451  0.1uF  [C0402-8]  142.39 99.12 90 bottom
C452  0.1uF  [C0402-8]  134.39 99.12 90 bottom
C453  0.1uF  [C0402-8]  130.39 99.12 90 bottom
C454  0.1uF  [C0402-8]  127.39 99.12 90 bottom
C455  0.1uF  [C0402-8]  126.39 99.12 90 bottom
C456  0.1uF  [C0402-8]  131.89 98.62 180 bottom
C457  0.1uF  [C0402-8]  128.89 98.62 0 bottom
C458  4.7uF  [C0402-8]  124.89 98.62 0 bottom
C459  0.1uF  [C0402]  184.28 98.62 0 bottom
C460  0.1uF  [C0402-8]  138.39 98.12 90 bottom
C461  0.1uF  [C0402-8]  137.39 98.12 90 bottom
C462  0.1uF  [C0402-8]  136.39 98.12 90 bottom
C463  0.1uF  [C0402-8]  140.39 98.12 270 bottom
C464  0.1uF  [C0402-8]  139.39 98.12 270 bottom
C465  0.1uF  [C0402-8]  128.88 97.62 180 bottom
C466  0.1uF  [C0402-8]  126.89 97.62 180 bottom
C467  4.7uF  [C0402-8]  122.89 97.62 180 bottom
C468  0.1uF  [C0402-8]  145.89 97.62 0 bottom
C469  0.1uF  [C0402-8]  132.89 97.62 0 bottom
C470  0.1uF  [C0402-8]  124.89 97.62 0 bottom
C471  0.1uF  [C0402-8]  131.39 97.12 90 bottom
C472  0.1uF  [C0402-8]  142.39 97.12 270 bottom
C473  0.1uF  [C0402-8]  130.39 97.12 270 bottom
C474  0.1uF  [C0402-8]  126.89 96.68 180 bottom
C475  0.1uF  [C0402-8]  128.89 96.62 0 bottom
C476  0.1uF  [C0402-8]  125.39 96.13 90 bottom
C477  4.7uF  [C0402-8]  124.39 96.13 90 bottom
C478  0.1uF  [C0402-8]  140.39 96.12 90 bottom
C479  0.1uF  [C0402-8]  135.39 96.12 90 bottom
C480  0.1uF  [C0402-8]  134.39 96.12 90 bottom
C481  0.1uF  [C0402-8]  141.39 96.12 270 bottom
C482  0.1uF  [C0402-8]  139.39 96.12 270 bottom
C483  0.1uF  [C0402-8]  138.39 96.12 270 bottom
C484  0.1uF  [C0402-8]  137.39 96.12 270 bottom
C485  0.1uF  [C0402-8]  136.39 96.12 270 bottom
C486  0.1uF  [C0402-8]  133.39 96.12 270 bottom
C487  0.1uF  [C0402]  184.28 95.69 0 bottom
C488  0.1uF  [C0402-8]  128.89 95.62 180 bottom
C489  0.1uF  [C0402-8]  126.89 95.62 180 bottom
C490  0.1uF  [C0402-8]  122.89 95.62 180 bottom
C491  0.1uF  [C0402-8]  130.89 95.62 0 bottom
C492  0.1uF  [C0402-8]  142.39 95.12 90 bottom
C493  0.1uF  [C0402-8]  144.89 94.62 0 bottom
C494  0.1uF  [C0402-8]  141.39 94.12 270 bottom
C495  0.1uF  [C0402-8]  140.39 94.12 270 bottom
C496  0.1uF  [C0402-8]  139.39 94.12 270 bottom
C497  0.1uF  [C0402-8]  138.39 94.12 270 bottom
C498  0.1uF  [C0402-8]  137.39 94.12 270 bottom
C499  0.1uF  [C0402-8]  136.39 94.12 270 bottom
C500  0.1uF  [C0402-8]  135.39 94.12 270 bottom
C501  0.1uF  [C0402-8]  134.39 94.12 270 bottom
C502  0.1uF  [C0402-8]  133.39 94.12 270 bottom
C503  0.1uF  [C0402-8]  132.39 94.12 270 bottom
C504  0.1uF  [C0402-8]  131.39 94.12 270 bottom
C505  0.1uF  [C0402-8]  130.39 94.12 270 bottom
C506  0.1uF  [C0402-8]  129.39 94.12 270 bottom
C507  0.1uF  [C0402-8]  128.39 94.12 270 bottom
C508  0.1uF  [C0402-8]  127.39 94.12 270 bottom
C509  0.1uF  [C0402-8]  126.39 94.12 270 bottom
C510  0.1uF  [C0402]  35.43 94.04 0 bottom
C511  0.1uF  [C0402]  35.43 92.9 0 bottom
C512  4.7uF  [C0402-8]  122.89 92.62 180 bottom
C513  0.1uF  [C0402-8]  124.89 92.62 0 bottom
C514  0.1uF  [C0402-8]  133.39 92.13 90 bottom
C515  0.1uF  [C0402-8]  141.39 92.12 90 bottom
C516  0.1uF  [C0402-8]  140.39 92.12 90 bottom
C517  0.1uF  [C0402-8]  139.39 92.12 90 bottom
C518  0.1uF  [C0402-8]  138.39 92.12 90 bottom
C519  0.1uF  [C0402-8]  137.39 92.12 90 bottom
C520  0.1uF  [C0402-8]  136.39 92.12 90 bottom
C521  0.1uF  [C0402-8]  135.39 92.12 90 bottom
C522  0.1uF  [C0402-8]  134.39 92.12 90 bottom
C523  0.1uF  [C0402-8]  132.39 92.12 90 bottom
C524  0.1uF  [C0402-8]  131.39 92.12 90 bottom
C525  0.1uF  [C0402-8]  130.39 92.12 90 bottom
C526  0.1uF  [C0402-8]  129.39 92.12 90 bottom
C527  0.1uF  [C0402-8]  128.39 92.12 90 bottom
C528  0.1uF  [C0402-8]  127.39 92.12 90 bottom
C529  0.1uF  [C0402-8]  126.39 92.12 90 bottom
C530  4.7uF  [C0402-8]  124.39 91.13 90 bottom
C531  0.1uF  [C0402]  184.28 91.12 0 bottom
C532  0.1uF  [C0402-8]  142.39 91.12 270 bottom
C533  0.1uF  [C0402-8]  125.39 91.11 270 bottom
C534  0.1uF  [C0402-8]  143.89 90.62 180 bottom
C535  0.1uF  [C0402-8]  122.89 90.62 180 bottom
C536  10uF  [C0402]  37.72 90.61 90 bottom
C537  0.1uF  [C0402]  36.58 90.61 90 bottom
C538  0.01uF  [C0402]  35.43 90.61 90 bottom
C539  0.1uF  [C0402]  34.29 90.61 90 bottom
C540  10uF  [C0402]  31.12 90.61 90 bottom
C541  0.1uF  [C0402]  29.97 90.61 90 bottom
C542  0.1uF  [C0402-8]  129.39 90.13 90 bottom
C543  0.1uF  [C0402-8]  128.39 90.13 90 bottom
C544  0.1uF  [C0402-8]  130.39 90.13 270 bottom
C545  0.1uF  [C0402-8]  140.39 90.12 90 bottom
C546  0.1uF  [C0402-8]  139.39 90.12 90 bottom
C547  0.1uF  [C0402-8]  137.39 90.12 90 bottom
C548  0.1uF  [C0402-8]  136.39 90.12 90 bottom
C549  0.1uF  [C0402-8]  135.39 90.12 90 bottom
C550  0.1uF  [C0402-8]  134.39 90.12 90 bottom
C551  0.1uF  [C0402-8]  141.39 90.12 270 bottom
C552  0.1uF  [C0402-8]  138.39 90.12 270 bottom
C553  4.7uF  [C0402-8]  133.39 90.12 270 bottom
C554  0.1uF  [C0402-8]  126.39 90.12 270 bottom
C555  0.1uF  [C0402-8]  131.39 90.11 90 bottom
C556  0.1uF  [C0402-8]  132.39 90.11 270 bottom
C557  0.1uF  [C0402-8]  127.39 90.11 270 bottom
C558  0.1uF  [C0402-8]  124.89 89.62 0 bottom
C559  0.1uF  [C0402-8]  121.89 88.62 180 bottom
C560  0.1uF  [C0402-8]  126.89 88.62 0 bottom
C561  0.1uF  [C0402-8]  123.89 88.62 0 bottom
C562  0.1uF  [C0402-8]  128.39 88.12 90 bottom
C563  0.1uF  [C0402-8]  140.39 88.12 270 bottom
C564  0.1uF  [C0402-8]  139.39 88.12 270 bottom
C565  0.1uF  [C0402-8]  138.39 88.12 270 bottom
C566  0.1uF  [C0402-8]  137.39 88.12 270 bottom
C567  0.1uF  [C0402-8]  136.39 88.12 270 bottom
C568  0.1uF  [C0402-8]  135.39 88.12 270 bottom
C569  0.1uF  [C0402-8]  134.39 88.12 270 bottom
C570  0.1uF  [C0402-8]  133.39 88.12 270 bottom
C571  0.1uF  [C0402-8]  132.39 88.12 270 bottom
C572  0.1uF  [C0402-8]  131.39 88.12 270 bottom
C573  0.1uF  [C0402-8]  130.39 88.12 270 bottom
C574  0.1uF  [C0402-8]  129.39 88.12 270 bottom
C575  0.1uF  [C0402-8]  125.39 88.12 270 bottom
C576  4.7uF  [C0402-8]  143.39 88.11 270 bottom
C577  0.1uF  [C0402-8]  126.39 87.12 270 bottom
C578  0.1uF  [C0402-8]  127.39 87.11 270 bottom
C579  0.1uF  [C0402-8]  128.89 86.62 180 bottom
C580  0.1uF  [C0402]  184.28 86.55 0 bottom
C581  0.1uF  [C0402-8]  124.39 86.12 270 bottom
C582  0.1uF  [C0402-8]  123.39 86.12 270 bottom
C583  0.1uF  [C0402-8]  122.39 86.12 270 bottom
C584  0.1uF  [C0402-8]  128.39 85.13 90 bottom
C585  0.1uF  [C0402-8]  131.88 84.62 180 bottom
C586  0.01uF  [C0402]  36.07 84.39 270 bottom
C587  0.1uF  [C0402]  34.92 84.39 270 bottom
C588  0.01uF  [C0402]  33.78 84.39 270 bottom
C589  0.1uF  [C0402]  32.64 84.39 270 bottom
C590  0.1uF  [C0402]  31.5 84.39 270 bottom
C591  4.7uF  [C0402-8]  128.88 83.62 0 bottom
C592  0.1uF  [C0402-8]  126.39 83.13 90 bottom
C593  0.1uF  [C0402]  184.28 81.98 0 bottom
C594  0.1uF  [C0402-8]  135.39 81.11 90 bottom
C595  0.1uF  [C0402-8]  131.39 81.12 270 bottom
C596  0.1uF  [C0402]  35.43 66.1 0 bottom
C597  0.1uF  [C0402]  35.43 64.96 0 bottom
C598  10uF  [C0402]  37.72 62.67 90 bottom
C599  0.1uF  [C0402]  36.58 62.67 90 bottom
C600  0.01uF  [C0402]  35.43 62.67 90 bottom
C601  0.1uF  [C0402]  34.29 62.67 90 bottom
C602  10uF  [C0402]  31.12 62.67 90 bottom
C603  0.1uF  [C0402]  29.97 62.67 90 bottom
C604  0.01uF  [C0402]  36.07 56.45 270 bottom
C605  0.1uF  [C0402]  34.92 56.45 270 bottom
C606  0.01uF  [C0402]  33.78 56.45 270 bottom
C607  0.1uF  [C0402]  32.64 56.45 270 bottom
C608  0.1uF  [C0402]  31.5 56.45 270 bottom
C609  0.1uF  [C0402]  216.41 53.78 0 bottom
C610  0.1uF  [C0402]  222.63 51.5 90 bottom
C611  10uF-08  [C0805]  219.96 49.97 180 bottom
C612  0.1uF  [C0402]  222.5 46.16 0 bottom
C613  0.1uF  [C0402]  222.5 44.89 0 bottom
C614  0.1uF  [C0402]  35.43 38.16 0 bottom
C615  0.1uF  [C0402]  35.43 37.02 0 bottom
C616  10uF  [C0402]  37.72 34.73 90 bottom
C617  0.1uF  [C0402]  36.58 34.73 90 bottom
C618  0.01uF  [C0402]  35.43 34.73 90 bottom
C619  0.1uF  [C0402]  34.29 34.73 90 bottom
C620  10uF  [C0402]  31.12 34.73 90 bottom
C621  0.1uF  [C0402]  29.97 34.73 90 bottom
C622  0.022uF  [C0402]  166.75 30.67 0 bottom
C623  47uF-08  [C0805]  156.21 30.42 270 bottom
C624  47uF-08  [C0805]  154.31 30.42 270 bottom
C625  47uF-08  [C0805]  152.4 30.42 270 bottom
C626  0.1uF  [C0402]  164.97 28.89 90 bottom
C627  0.01uF  [C0402]  36.07 28.51 270 bottom
C628  0.1uF  [C0402]  34.92 28.51 270 bottom
C629  0.01uF  [C0402]  33.78 28.51 270 bottom
C630  0.1uF  [C0402]  32.64 28.51 270 bottom
C631  0.1uF  [C0402]  31.5 28.51 270 bottom
C632  4.7uF-06  [C0603]  165.23 16.32 0 bottom
C661  0.1uF  [C0402-8]  85.6 103.14 0 bottom
C662  0.1uF  [C0402-8]  85.6 102.25 0 bottom
C663  0.1uF  [C0402-8]  89.76 104.84 0 bottom
C664  0.1uF  [C0402-8]  89.76 103.95 0 bottom
C665  0.1uF  [C0402-8]  85.6 105.73 0 bottom
C666  0.1uF  [C0402-8]  85.6 106.62 0 bottom
C667  0.1uF  [C0402-8]  89.76 107.53 0 bottom
C668  0.1uF  [C0402-8]  89.76 108.42 0 bottom
C700  47uF-08  [C0805]  192.02 43.05 90 top
C701  47uF-08  [C0805]  194.31 43.05 90 top
C702  4.7uF-08  [C0603]  187.58 43.05 90 top
C703  4.7uF-08  [C0603]  189.74 43.05 90 top
C704  10uF  [C0402]  22.23 135.32 90 top
D1  B260A  [SMA_DIODES]  18.77 125.41 90 top
D2  B260A  [SMA_DIODES]  18.77 97.47 90 top
D3  B260A  [SMA_DIODES]  18.77 69.53 90 top
D4  B260A  [SMA_DIODES]  18.77 41.59 90 top
FAN1  Header_2_2.54  [CONN1X2_2_54]  251.84 91.76 90 top
FAN2  Header_2_2.54  [CONN1X2_2_54]  251.84 73.47 90 top
HDMI1  CONN_HDMI  [HDMI]  9.88 145.47 270 top
J1  MECHANICAL_HOLE  [TOOL_1H_8D_C_LC_02]  88.9 161.61 0 top
J2  MECHANICAL_HOLE  [TOOL_1H_8D_C_LC_02]  139.7 161.61 0 top
J3  MECHANICAL_HOLE  [TOOL_1H_8D_C_LC_02]  190.5 161.61 0 top
J4  CONN5x2  [CONN10]  152.4 149.93 0 top
J5  -  [CON2]  39.5 125.79 0 top
J6  CONN_HDMI  [HDMI]  9.88 117.53 270 top
J7  -  [CON2]  39.5 97.85 0 top
J8  CONN_HDMI  [HDMI]  9.88 89.59 270 top
J9  -  [CON2]  39.5 69.91 0 top
J10  CONN_HDMI  [HDMI]  9.88 61.65 270 top
J11  CON7  [CONN7]  233.87 55.94 270 top
J12  -  [CON2]  39.5 41.97 0 top
J13  Header_4_2.54  [CONN1X4_2_54]  241.94 36.39 270 top
J14  CONN_HDMI  [HDMI]  9.88 33.71 270 top
J15  -  [3PIN_POWER]  251.05 15.79 270 top
J16  MECHANICAL_HOLE  [TOOL_1H_8D_C_LC_02]  88.9 8.45 0 top
J17  MECHANICAL_HOLE  [TOOL_1H_8D_C_LC_02]  139.7 8.45 0 top
J18  MECHANICAL_HOLE  [TOOL_1H_8D_C_LC_02]  190.5 8.45 0 top
JA1  VH4  [DRILL_1X4_3_96]  251.84 26.86 90 top
JT1  -  [ERNI_973046]  253.7 142.93 90 top
L1  FB220-06  [R0603]  24.89 135.06 90 top
L2  0.47uH-17.5A  [L_GFB_58X28]  197.1 133.54 180 top
L4  0.47uH-17.5A  [L_GFB_58X28]  197.1 91.63 180 top
L5  BEAD-04  [R0402]  82.68 86.17 270 top
L6  BEAD-04  [R0402]  130.05 61.66 180 top
L7  2.2uH  [IND4X4]  88.65 40.58 0 top
L8  FB120-08  [R0805]  115.95 36.64 90 top
L9  FB120-08  [R0805]  118.49 36.64 90 top
L10  2.2uH  [IND4X4]  201.17 30.8 90 top
L11  0.47uH-23A  [L_GFB_58X28]  160.4 30.04 270 top
L12  0.47uH-17.5A  [L_GFB_58X28]  68.58 30.16 90 top
L13  0.47uH-17.5A  [L_GFB_58X28]  95.25 30.16 90 top
L14  0.47uH-17.5A  [L_GFB_58X28]  114.17 30.16 90 top
L15  0.47uH-17.5A  [L_GFB_58X28]  180.97 30.16 90 top
L16  FB220-06  [MY_0603_RES]  38.48 120.71 0 bottom
L17  FB220-06  [MY_0603_RES]  38.48 110.81 0 bottom
L18  FB220-06  [MY_0603_RES]  38.48 92.77 0 bottom
L19  FB220-06  [MY_0603_RES]  38.48 82.87 0 bottom
L20  BEAD-04  [R0402]  138.43 75.25 0 bottom
L21  FB220-06  [MY_0603_RES]  38.48 64.83 0 bottom
L22  FB220-06  [MY_0603_RES]  38.48 54.93 0 bottom
L23  FB220-06  [MY_0603_RES]  38.48 36.89 0 bottom
L24  FB220-06  [MY_0603_RES]  38.48 26.99 0 bottom
L34  FB120-08  [R0805]  191.26 37.97 90 top
L35  FB120-08  [R0805]  193.68 37.97 90 top
M1  MARK  [ID-BOARD]  254.76 163.77 0 top
M2  MARK  [ID-BOARD]  22.35 162.88 0 top
M3  MARK  [ID-BOARD]  119.25 115.25 0 top
M4  MARK  [ID-BOARD]  150.62 68.77 0 top
M5  MARK  [ID-BOARD]  22.48 10.6 0 top
M6  MARK  [ID-BOARD]  254.76 163.77 180 bottom
M*  -  [unnamed#3]  22.48 10.6 180 bottom
M*#2  -  [unnamed#3]  22.35 162.88 180 bottom
NOREF  VAL  [unnamed]  133.89 93.12 0 top
NOREF#2  VAL  [unnamed]  133.89 93.12 90 top
NOREF#3  -  [#2]  334.52 143.8 0 top
P1  10AX027 F34  [BGA1152_PAD18]  133.89 93.12 180 top
Q1  BSS123LT1  [SOT-23]  19.11 155.13 270 top
Q2  BSS123LT1  [SOT-23]  25.97 154.87 90 top
Q3  BSS123LT1  [SOT-23]  22.58 121.47 270 top
Q4  BSS123LT1  [SOT-23]  22.58 93.53 270 top
Q5  BSS123LT1  [SOT-23]  22.58 65.59 270 top
Q6  BSS123LT1  [SOT-23]  22.58 37.65 270 top
R1  2K  [R0402]  15.02 164.3 180 top
R2  300  [R0402]  15.02 162.98 180 top
R3  1M  [R0402]  96.39 162.88 180 top
R4  1M  [R0402]  147.19 162.88 180 top
R5  1M  [R0402]  197.99 162.88 180 top
R6  0R-NC  [R0402]  18.67 152.84 0 top
R7  1K  [R0402]  21.72 155.38 270 top
R8  1K  [R0402]  23.05 155.38 270 top
R9  10K  [R0402]  16.44 155.13 270 top
R10  1M  [R0402]  11.43 154.88 180 top
R11  10K  [R0402]  28.51 154.87 270 top
R12  0R  [R0402]  18.67 151.7 0 top
R13  200K  [R0402]  21.53 150.27 270 top
R14  1K  [R0402]  152.96 147.66 180 top
R15  10K  [R0402]  158.04 147.66 180 top
R16  49.9R  [R0402]  19.81 148.02 270 top
R17  49.9R  [R0402]  19.81 145.73 90 top
R18  49.9R  [R0402]  23.24 145.4 270 top
R19  0  [R0402]  114.17 143.95 180 top
R20  49.9R  [R0402]  23.24 143.09 90 top
R21  49.9R  [R0402]  21.21 141.92 270 top
R22  100K  [R0402]  114.17 142.81 180 top
R23  240  [R0402]  173.99 142.05 270 top
R24  49.9R  [R0402]  21.21 139.64 90 top
R25  49.9R  [R0402]  30.35 135.7 270 top
R26  49.9R  [R0402]  31.5 141.03 270 top
R27  49.9R  [R0402]  32.64 141.03 270 top
R28  49.9R  [R0402]  35.05 141.03 270 top
R29  49.9R  [R0402]  36.32 141.03 270 top
R30  50  [R0402]  131.06 140.78 270 top
R31  50  [R0402]  132.21 140.78 270 top
R32  50  [R0402]  133.35 140.78 270 top
R33  50  [R0402]  134.49 140.78 270 top
R34  50  [R0402]  135.64 140.78 270 top
R35  50  [R0402]  136.78 140.78 270 top
R36  50  [R0402]  137.92 140.78 270 top
R37  50  [R0402]  139.06 140.78 270 top
R38  10K  [R0402]  116.84 140.65 0 top
R39  49.9R  [R0402]  30.35 133.41 90 top
R40  10K  [R0402]  118.62 140.14 270 top
R41  10K  [R0402]  151.48 136.18 270 top
R42  22  [R0402]  152.62 136.18 90 top
R43  10K  [R0402]  153.76 136.18 90 top
R44  49.9K  [R0402]  208.53 135.7 0 top
R45  52.3K  [R0402]  210.82 135.7 0 top
R46  10K  [R0402]  211.33 133.92 270 top
R47  22R  [R0402]  245.87 133.29 0 top
R48  240  [R0402]  98.42 133.03 0 top
R49  240  [R0402]  113.67 133.03 0 top
R50  240  [R0402]  128.91 132.27 0 top
R51  22R  [R0402]  245.87 132.14 0 top
R52  100K  [R0402]  208.53 131.25 180 top
R53  22R  [R0402]  245.87 131 0 top
R54  22R  [R0402]  245.87 129.86 0 top
R55  150K  [R0402]  208.03 129.48 270 top
R56  4.7K  [R0402]  24.48 128.71 90 top
R57  0R  [R0402]  25.63 128.71 90 top
R58  1M  [R0402]  11.43 126.94 180 top
R59  240  [R0402]  173.99 126.81 270 top
R60  68.1K  [R0402]  24.48 126.42 90 top
R61  100K  [R0402]  183.77 126.17 90 top
R62  0  [R0402]  184.91 126.17 90 top
R63  0  [R0402]  14.99 123.76 0 top
R64  10K  [R0402]  181.61 123.51 270 top
R65  7.06K  [R0402]  29.21 122.49 270 top
R66  65K_NC  [R0402]  30.35 122.49 270 top
R67  65K_NC  [R0402]  31.5 122.49 90 top
R68  65K_NC  [R0402]  32.64 122.49 90 top
R69  65K_NC  [R0402]  33.78 122.49 270 top
R70  65K_NC  [R0402]  34.92 122.49 90 top
R71  65K  [R0402]  36.07 122.49 270 top
R72  2K  [R0402]  37.21 122.49 270 top
R73  0R  [R0402]  38.35 122.49 90 top
R74  2K  [R0402]  39.5 122.49 270 top
R75  0R  [R0402]  40.64 122.49 90 top
R76  10K  [R0402]  181.1 121.73 180 top
R77  10K  [R0402]  25.12 121.6 270 top
R78  10K  [R0402]  19.56 121.48 90 top
R80  49.9R  [R0402]  21.59 118.94 180 top
R82  49.9R  [R0402]  21.59 117.41 180 top
R83  49.9R  [R0402]  24.51 117.28 180 top
R84  49.9R  [R0402]  24.51 115.76 180 top
R85  49.9R  [R0402]  21.59 115.63 180 top
R86  49.9R  [R0402]  21.59 114.11 180 top
R87  49.9R  [R0402]  24.51 113.98 180 top
R88  49.9R  [R0402]  24.51 112.46 180 top
R89  240  [R0402]  173.23 111.57 270 top
R90  0R  [R0402]  35.05 109.79 180 top
R91  0R  [R0402]  37.47 109.79 0 top
R92  50  [R0402]  181.74 109.54 180 top
R93  0R_NC  [R0402]  29.84 109.28 90 top
R94  0R_NC  [R0402]  30.99 109.28 90 top
R95  500K  [R0402]  33.27 109.28 270 top
R96  2K  [R0402]  46.99 108.39 270 top
R97  50  [R0402]  181.74 108.39 180 top
R98  0R_NC  [R0402]  35.56 108.01 270 top
R99  0R_NC  [R0402]  36.96 108.01 270 top
R100  47K  [R0402]  38.99 108.01 180 top
R101  47K  [R0402]  29.21 107.51 180 top
R102  47K  [R0402]  31.62 107.51 0 top
R103  50  [R0402]  181.74 107.25 180 top
R104  47K  [R0402]  38.96 106.74 180 top
R105  2K  [R0402]  46.99 106.11 90 top
R106  50  [R0402]  181.74 106.11 180 top
R107  0R  [R0402]  29.72 105.73 270 top
R108  0R  [R0402]  31.12 105.73 270 top
R109  50  [R0402]  181.74 104.97 180 top
R110  200K  [R0402]  38.96 104.33 180 top
R111  50  [R0402]  181.74 103.82 180 top
R112  50  [R0402]  181.74 102.68 180 top
R113  50  [R0402]  181.74 101.54 180 top
R114  4.7K  [R0402]  24.48 100.77 90 top
R115  0R  [R0402]  25.63 100.77 90 top
R116  1M  [R0402]  11.43 99 180 top
R117  68.1K  [R0402]  24.48 98.48 90 top
R118  22  [R0402]  90.3 96.33 270 top
R119  1K  [R0402]  87.31 96.2 90 top
R120  0  [R0402]  14.99 95.82 0 top
R121  240  [R0402]  173.48 95.06 270 top
R122  7.06K  [R0402]  29.21 94.55 270 top
R123  65K_NC  [R0402]  30.35 94.55 270 top
R124  65K_NC  [R0402]  31.5 94.55 90 top
R125  65K_NC  [R0402]  32.64 94.55 90 top
R126  65K_NC  [R0402]  33.78 94.55 270 top
R127  65K_NC  [R0402]  34.92 94.55 90 top
R128  65K  [R0402]  36.07 94.55 270 top
R129  2K  [R0402]  37.21 94.55 270 top
R130  0R  [R0402]  38.35 94.55 90 top
R131  2K  [R0402]  39.5 94.55 270 top
R132  0R  [R0402]  40.64 94.55 90 top
R133  4.7K  [R0402]  95 94.17 90 top
R134  0  [R0402]  90.3 93.92 90 top
R135  49.9K  [R0402]  208.53 93.79 0 top
R136  52.3K  [R0402]  210.82 93.79 0 top
R137  10K  [R0402]  25.12 93.66 270 top
R138  10K  [R0402]  19.81 93.54 90 top
R139  50  [R0402]  181.74 92.9 180 top
R140  10K  [R0402]  211.33 92.01 270 top
R141  50  [R0402]  181.74 91.76 180 top
R142  49.9R  [R0402]  21.59 91 180 top
R143  50  [R0402]  181.74 90.61 180 top
R144  49.9R  [R0402]  21.59 89.47 180 top
R145  50  [R0402]  181.74 89.47 180 top
R146  49.9R  [R0402]  24.51 89.34 180 top
R147  10K  [R0402]  208.53 89.34 180 top
R148  50  [R0402]  181.74 88.33 180 top
R149  49.9R  [R0402]  24.51 87.82 180 top
R150  49.9R  [R0402]  21.59 87.69 180 top
R151  45K  [R0402]  208.03 87.57 270 top
R152  50  [R0402]  181.74 87.19 180 top
R153  49.9R  [R0402]  21.59 86.17 180 top
R154  22R  [R0402]  86.11 86.17 270 top
R155  49.9R  [R0402]  24.51 86.04 180 top
R156  50  [R0402]  181.74 86.04 180 top
R157  50  [R0402]  181.74 84.9 180 top
R158  49.9R  [R0402]  24.51 84.52 180 top
R159  0R  [R0402]  35.05 81.85 180 top
R160  0R  [R0402]  37.47 81.85 0 top
R161  0R_NC  [R0402]  29.84 81.34 90 top
R162  0R_NC  [R0402]  30.99 81.34 90 top
R163  500K  [R0402]  33.27 81.34 270 top
R164  2K  [R0402]  46.99 80.45 270 top
R165  0R_NC  [R0402]  35.56 80.07 270 top
R166  0R_NC  [R0402]  36.96 80.07 270 top
R167  47K  [R0402]  38.99 80.07 180 top
R168  240  [R0402]  173.23 79.82 270 top
R169  47K  [R0402]  29.21 79.57 180 top
R170  47K  [R0402]  31.62 79.57 0 top
R171  47K  [R0402]  38.96 78.8 180 top
R172  2K  [R0402]  46.99 78.17 90 top
R173  0R  [R0402]  29.72 77.79 270 top
R174  0R  [R0402]  31.12 77.79 270 top
R175  200K  [R0402]  38.96 76.39 180 top
R176  4.7K  [R0402]  24.48 72.83 90 top
R177  0R  [R0402]  25.63 72.83 90 top
R178  10K  [R0402]  185.55 72.2 0 top
R179  22R  [C0402-8]  126.56 71.57 270 top
R180  22R  [C0402-8]  127.96 71.57 270 top
R181  22R  [C0402-8]  130.17 71.57 270 top
R182  22R  [C0402-8]  131.06 71.57 270 top
R183  22R  [C0402-8]  131.95 71.57 270 top
R184  22R  [C0402-8]  132.84 71.57 270 top
R185  22R  [C0402-8]  133.73 71.57 270 top
R186  22R  [C0402-8]  134.61 71.57 270 top
R187  22R  [C0402-8]  135.5 71.57 270 top
R188  22R  [C0402-8]  136.39 71.57 270 top
R189  22R  [C0402-8]  137.28 71.57 270 top
R190  22R  [C0402-8]  138.17 71.57 270 top
R191  22R  [C0402-8]  139.06 71.57 270 top
R192  22R  [C0402-8]  125.68 71.56 270 top
R193  1M  [R0402]  11.43 71.06 180 top
R194  68.1K  [R0402]  24.48 70.54 90 top
R195  10K  [R0402]  185.04 70.42 90 top
R196  0  [R0402]  14.99 67.88 0 top
R197  0  [R0402]  181.74 67.75 270 top
R198  100K  [R0402]  182.88 67.75 270 top
R199  7.06K  [R0402]  29.21 66.61 270 top
R200  65K_NC  [R0402]  30.35 66.61 270 top
R201  65K_NC  [R0402]  31.5 66.61 90 top
R202  65K_NC  [R0402]  32.64 66.61 90 top
R203  65K_NC  [R0402]  33.78 66.61 270 top
R204  65K_NC  [R0402]  34.92 66.61 90 top
R205  65K  [R0402]  36.07 66.61 270 top
R206  2K  [R0402]  37.21 66.61 270 top
R207  0R  [R0402]  38.35 66.61 90 top
R208  2K  [R0402]  39.5 66.61 270 top
R209  0R  [R0402]  40.64 66.61 90 top
R210  10K  [R0402]  25.12 65.72 270 top
R211  10K  [R0402]  19.94 65.6 90 top
R212  240  [R0402]  173.23 64.58 270 top
R213  49.9R  [R0402]  21.59 63.06 180 top
R214  49.9R  [R0402]  21.59 61.53 180 top
R215  49.9R  [R0402]  24.51 61.4 180 top
R216  4.7K  [R0402]  218.95 60.26 270 top
R217  49.9R  [R0402]  24.51 59.88 180 top
R218  49.9R  [R0402]  21.59 59.75 180 top
R219  49.9R  [R0402]  21.59 58.23 180 top
R220  49.9R  [R0402]  24.51 58.1 180 top
R221  10K  [R0402]  231.65 57.85 270 top
R222  1K  [R0402]  140.59 57.72 0 top
R223  49.9R  [R0402]  24.51 56.58 180 top
R224  4.7K  [R0402]  229.24 55.69 0 top
R225  10K  [R0402]  231.65 55.18 270 top
R226  0R  [R0402]  35.05 53.91 180 top
R227  0R  [R0402]  37.47 53.91 0 top
R228  0  [R0402]  136.53 53.91 0 top
R229  22  [R0402]  138.81 53.91 180 top
R230  0R_NC  [R0402]  29.84 53.4 90 top
R231  0R_NC  [R0402]  30.99 53.4 90 top
R232  500K  [R0402]  33.27 53.4 270 top
R233  2K  [R0402]  46.99 52.51 270 top
R234  0R_NC  [R0402]  35.56 52.13 270 top
R235  0R_NC  [R0402]  36.96 52.13 270 top
R236  47K  [R0402]  38.99 52.13 180 top
R237  10K  [R0402]  210.31 50.99 180 top
R238  10K  [R0402]  210.31 52.39 0 top
R239  47K  [R0402]  29.21 51.63 180 top
R240  47K  [R0402]  31.62 51.63 0 top
R241  47K  [R0402]  38.96 50.86 180 top
R242  2K  [R0402]  46.99 50.23 90 top
R243  0R  [R0402]  29.72 49.85 270 top
R244  0R  [R0402]  31.12 49.85 270 top
R245  10K  [R0402]  210.31 49.72 0 top
R246  4.7K  [R0402]  138.18 49.34 180 top
R247  10K  [R0402]  210.31 48.58 0 top
R248  200K  [R0402]  38.96 48.45 180 top
R249  4.7K  [R0402]  210.31 47.31 180 top
R250  4.7K  [R0402]  210.31 46.16 180 top
R251  4.7K  [R0402]  24.48 44.89 90 top
R252  0R  [R0402]  25.63 44.89 90 top
R253  1M  [R0402]  11.43 43.12 180 top
R254  0R  [R0402]  218.06 42.61 270 top
R255  4.7K  [R0402]  219.46 42.61 270 top
R256  4.7K  [R0402]  220.85 42.61 270 top
R257  68.1K  [R0402]  24.48 42.6 90 top
R258  0  [R0402]  14.99 39.94 0 top
R259  10K  [R0402]  82.55 39.05 180 top
R260  10K  [R0402]  84.84 39.05 0 top
R261  7.06K  [R0402]  29.21 38.67 270 top
R262  65K_NC  [R0402]  30.35 38.67 270 top
R263  65K_NC  [R0402]  31.5 38.67 90 top
R264  65K_NC  [R0402]  32.64 38.67 90 top
R265  65K_NC  [R0402]  33.78 38.67 270 top
R266  65K_NC  [R0402]  34.92 38.67 90 top
R267  65K  [R0402]  36.07 38.67 270 top
R268  2K  [R0402]  37.21 38.67 270 top
R269  0R  [R0402]  38.35 38.67 90 top
R270  2K  [R0402]  39.5 38.67 270 top
R271  0R  [R0402]  40.64 38.67 90 top
R272  20K  [R0402]  82.55 37.91 180 top
R273  10K  [R0402]  25.12 37.78 270 top
R274  10K  [R0402]  19.94 37.66 90 top
